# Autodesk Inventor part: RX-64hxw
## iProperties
Created: 2009-01
Part Number: RX-64hxw
Material: Aluminum-6061
Document SubType Name: Sheet Metal
Designer: Administrator
Density: 1 g/cm^3
Author: Administrator
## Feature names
1. Hole1
2. Hole2
3. Corner Round1
4. Corner Round2
5. Plate1
6. Plate2
7. Bend1
8. Plate3
9. Bend2
10. Cut1
11. Cut2
